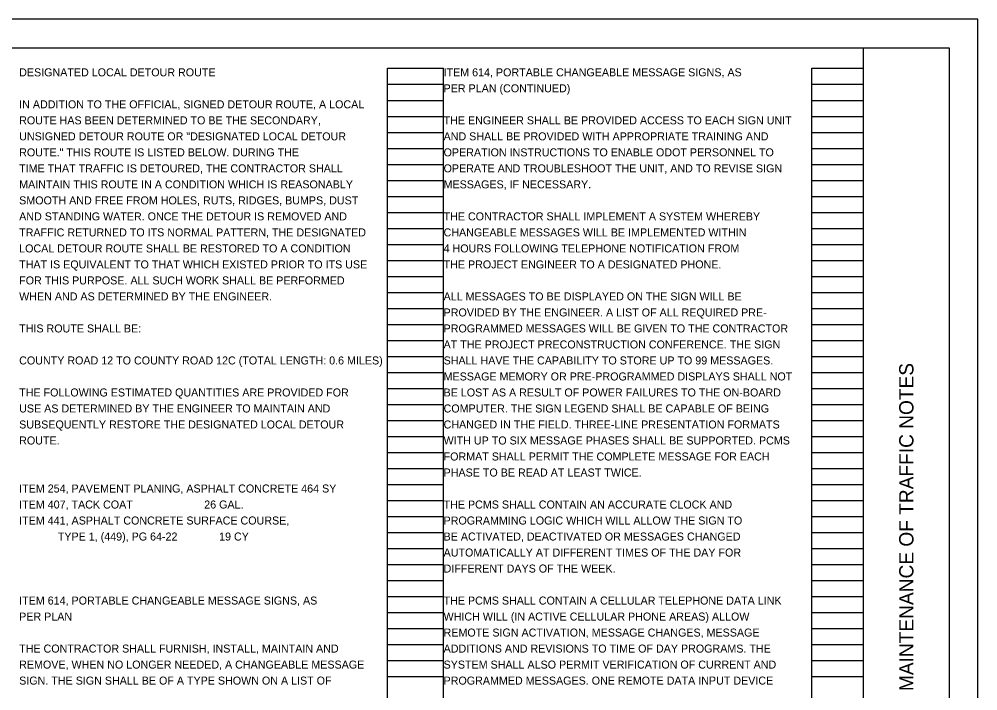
# Model space of a CAD drawing. Extents: x 0 to 34, y 0 to 22.
# Drawn here: x 17.24 to 34, y 10.25 to 22 of the extents above; entities that cross this region are included whole.
import ezdxf

# ---------------------------------------------------------------- set-up
doc = ezdxf.new("R2010")
doc.units = 0
for name, color, linetype in [('SH_Border', 7, 'Continuous'), ('SH_Cut_Line', 7, 'Continuous'), ('SH_Data', 7, 'Continuous'), ('SH_Text', 7, 'Continuous')]:
    doc.layers.add(name, color=color, linetype=linetype)

msp = doc.modelspace()

# ---------------------------------------------------------------- linework, layer by layer
at = {"layer": 'SH_Border'}
msp.add_line((32, 0.5), (32, 21.5), dxfattribs=at)
msp.add_lwpolyline([(1.5, 21.5), (33.5, 21.5), (33.5, 0.5), (1.5, 0.5)], close=True, dxfattribs=at)
at = {"layer": 'SH_Cut_Line'}
msp.add_lwpolyline([(0, 0), (34, 0), (34, 22), (0, 22)], close=True, dxfattribs=at)
at = {"layer": 'SH_Data'}
for p, q in [((23.68, 0.98), (23.68, 21.14)), ((23.68, 21.14), (24.66, 21.14)), ((24.66, 0.98), (24.66, 21.14)), ((31.1, 0.98), (31.1, 21.14)), ((31.1, 21.14), (32, 21.14)), ((32, 0.98), (32, 21.14)), ((23.68, 20.86), (24.66, 20.86)), ((31.1, 20.86), (32, 20.86)), ((23.68, 20.58), (24.66, 20.58)), ((31.1, 20.58), (32, 20.58)), ((23.68, 20.3), (24.66, 20.3)), ((31.1, 20.3), (32, 20.3)), ((23.68, 20.02), (24.66, 20.02)), ((31.1, 20.02), (32, 20.02)), ((23.68, 19.74), (24.66, 19.74)), ((31.1, 19.74), (32, 19.74)), ((23.68, 19.46), (24.66, 19.46)), ((31.1, 19.46), (32, 19.46)), ((23.68, 19.18), (24.66, 19.18)), ((31.1, 19.18), (32, 19.18)), ((23.68, 18.9), (24.66, 18.9)), ((31.1, 18.9), (32, 18.9)), ((23.68, 18.62), (24.66, 18.62)), ((31.1, 18.62), (32, 18.62)), ((23.68, 18.34), (24.66, 18.34)), ((31.1, 18.34), (32, 18.34)), ((23.68, 18.06), (24.66, 18.06)), ((31.1, 18.06), (32, 18.06)), ((23.68, 17.78), (24.66, 17.78)), ((31.1, 17.78), (32, 17.78)), ((23.68, 17.5), (24.66, 17.5)), ((31.1, 17.5), (32, 17.5)), ((23.68, 17.22), (24.66, 17.22)), ((31.1, 17.22), (32, 17.22)), ((23.68, 16.94), (24.66, 16.94)), ((31.1, 16.94), (32, 16.94)), ((23.68, 16.66), (24.66, 16.66)), ((31.1, 16.66), (32, 16.66)), ((23.68, 16.38), (24.66, 16.38)), ((31.1, 16.38), (32, 16.38)), ((23.68, 16.1), (24.66, 16.1)), ((31.1, 16.1), (32, 16.1)), ((23.68, 15.82), (24.66, 15.82)), ((31.1, 15.82), (32, 15.82)), ((23.68, 15.54), (24.66, 15.54)), ((31.1, 15.54), (32, 15.54)), ((23.68, 15.26), (24.66, 15.26)), ((31.1, 15.26), (32, 15.26)), ((23.68, 14.98), (24.66, 14.98)), ((31.1, 14.98), (32, 14.98)), ((23.68, 14.7), (24.66, 14.7)), ((31.1, 14.7), (32, 14.7)), ((23.68, 14.42), (24.66, 14.42)), ((31.1, 14.42), (32, 14.42)), ((23.68, 14.14), (24.66, 14.14)), ((31.1, 14.14), (32, 14.14)), ((23.68, 13.86), (24.66, 13.86)), ((31.1, 13.86), (32, 13.86)), ((23.68, 13.58), (24.66, 13.58)), ((31.1, 13.58), (32, 13.58)), ((23.68, 13.3), (24.66, 13.3)), ((31.1, 13.3), (32, 13.3)), ((23.68, 13.02), (24.66, 13.02)), ((31.1, 13.02), (32, 13.02)), ((23.68, 12.74), (24.66, 12.74)), ((31.1, 12.74), (32, 12.74)), ((23.68, 12.46), (24.66, 12.46)), ((31.1, 12.46), (32, 12.46)), ((23.68, 12.18), (24.66, 12.18)), ((31.1, 12.18), (32, 12.18)), ((23.68, 11.9), (24.66, 11.9)), ((31.1, 11.9), (32, 11.9)), ((23.68, 11.62), (24.66, 11.62)), ((31.1, 11.62), (32, 11.62)), ((23.68, 11.34), (24.66, 11.34)), ((31.1, 11.34), (32, 11.34)), ((23.68, 11.06), (24.66, 11.06)), ((31.1, 11.06), (32, 11.06)), ((23.68, 10.78), (24.66, 10.78)), ((31.1, 10.78), (32, 10.78)), ((23.68, 10.5), (24.66, 10.5)), ((31.1, 10.5), (32, 10.5))]:
    msp.add_line(p, q, dxfattribs=at)

# ---------------------------------------------------------------- texts
msp.add_text('MAINTENANCE OF TRAFFIC NOTES', height=0.25, rotation=90, dxfattribs=at).set_placement((32.875, 10.247))
at = {"layer": 'SH_Text'}
for s, p in [('DESIGNATED LOCAL DETOUR ROUTE', (17.24, 21)), ('ITEM 614, PORTABLE CHANGEABLE MESSAGE SIGNS, AS', (24.66, 21)), ('PER PLAN (CONTINUED)', (24.66, 20.72)), ('IN ADDITION TO THE OFFICIAL, SIGNED DETOUR ROUTE, A LOCAL', (17.24, 20.44)), ('ROUTE HAS BEEN DETERMINED TO BE THE SECONDARY,', (17.24, 20.16)), ('THE ENGINEER SHALL BE PROVIDED ACCESS TO EACH SIGN UNIT', (24.66, 20.16)), ('UNSIGNED DETOUR ROUTE OR "DESIGNATED LOCAL DETOUR', (17.24, 19.88)), ('AND SHALL BE PROVIDED WITH APPROPRIATE TRAINING AND', (24.66, 19.88)), ('ROUTE." THIS ROUTE IS LISTED BELOW. DURING THE', (17.24, 19.6)), ('OPERATION INSTRUCTIONS TO ENABLE ODOT PERSONNEL TO', (24.66, 19.6)), ('TIME THAT TRAFFIC IS DETOURED, THE CONTRACTOR SHALL', (17.24, 19.32)), ('OPERATE AND TROUBLESHOOT THE UNIT, AND TO REVISE SIGN', (24.66, 19.32)), ('MAINTAIN THIS ROUTE IN A CONDITION WHICH IS REASONABLY', (17.24, 19.04)), ('MESSAGES, IF NECESSARY.', (24.66, 19.04)), ('SMOOTH AND FREE FROM HOLES, RUTS, RIDGES, BUMPS, DUST', (17.24, 18.76)), ('AND STANDING WATER. ONCE THE DETOUR IS REMOVED AND', (17.24, 18.48)), ('THE CONTRACTOR SHALL IMPLEMENT A SYSTEM WHEREBY', (24.66, 18.48)), ('TRAFFIC RETURNED TO ITS NORMAL PATTERN, THE DESIGNATED', (17.24, 18.2)), ('CHANGEABLE MESSAGES WILL BE IMPLEMENTED WITHIN', (24.66, 18.2)), ('LOCAL DETOUR ROUTE SHALL BE RESTORED TO A CONDITION', (17.24, 17.92)), ('4 HOURS FOLLOWING TELEPHONE NOTIFICATION FROM', (24.66, 17.92)), ('THAT IS EQUIVALENT TO THAT WHICH EXISTED PRIOR TO ITS USE', (17.24, 17.64)), ('THE PROJECT ENGINEER TO A DESIGNATED PHONE.', (24.66, 17.64)), ('FOR THIS PURPOSE. ALL SUCH WORK SHALL BE PERFORMED', (17.24, 17.36)), ('WHEN AND AS DETERMINED BY THE ENGINEER.', (17.24, 17.08)), ('ALL MESSAGES TO BE DISPLAYED ON THE SIGN WILL BE', (24.66, 17.08)), ('PROVIDED BY THE ENGINEER. A LIST OF ALL REQUIRED PRE-', (24.66, 16.8)), ('THIS ROUTE SHALL BE:', (17.24, 16.52)), ('PROGRAMMED MESSAGES WILL BE GIVEN TO THE CONTRACTOR', (24.66, 16.52)), ('AT THE PROJECT PRECONSTRUCTION CONFERENCE. THE SIGN', (24.66, 16.24)), ('COUNTY ROAD 12 TO COUNTY ROAD 12C (TOTAL LENGTH: 0.6 MILES)', (17.24, 15.96)), ('SHALL HAVE THE CAPABILITY TO STORE UP TO 99 MESSAGES.', (24.66, 15.96)), ('MESSAGE MEMORY OR PRE-PROGRAMMED DISPLAYS SHALL NOT', (24.66, 15.68)), ('THE FOLLOWING ESTIMATED QUANTITIES ARE PROVIDED FOR', (17.24, 15.4)), ('BE LOST AS A RESULT OF POWER FAILURES TO THE ON-BOARD', (24.66, 15.4)), ('USE AS DETERMINED BY THE ENGINEER TO MAINTAIN AND', (17.24, 15.12)), ('COMPUTER. THE SIGN LEGEND SHALL BE CAPABLE OF BEING', (24.66, 15.12)), ('SUBSEQUENTLY RESTORE THE DESIGNATED LOCAL DETOUR', (17.24, 14.84)), ('CHANGED IN THE FIELD. THREE-LINE PRESENTATION FORMATS', (24.66, 14.84)), ('ROUTE.', (17.24, 14.56)), ('WITH UP TO SIX MESSAGE PHASES SHALL BE SUPPORTED. PCMS', (24.66, 14.56)), ('FORMAT SHALL PERMIT THE COMPLETE MESSAGE FOR EACH', (24.66, 14.28)), ('PHASE TO BE READ AT LEAST TWICE.', (24.66, 14)), ('ITEM 254, PAVEMENT PLANING, ASPHALT CONCRETE 464 SY', (17.24, 13.72)), ('ITEM 407, TACK COAT                        26 GAL.', (17.24, 13.44)), ('THE PCMS SHALL CONTAIN AN ACCURATE CLOCK AND', (24.66, 13.44)), ('ITEM 441, ASPHALT CONCRETE SURFACE COURSE,', (17.24, 13.16)), ('PROGRAMMING LOGIC WHICH WILL ALLOW THE SIGN TO', (24.66, 13.16)), ('             TYPE 1, (449), PG 64-22              19 CY', (17.24, 12.88)), ('BE ACTIVATED, DEACTIVATED OR MESSAGES CHANGED', (24.66, 12.88)), ('AUTOMATICALLY AT DIFFERENT TIMES OF THE DAY FOR', (24.66, 12.6)), ('DIFFERENT DAYS OF THE WEEK.', (24.66, 12.32)), ('ITEM 614, PORTABLE CHANGEABLE MESSAGE SIGNS, AS', (17.24, 11.76)), ('THE PCMS SHALL CONTAIN A CELLULAR TELEPHONE DATA LINK', (24.66, 11.76)), ('PER PLAN', (17.24, 11.48)), ('WHICH WILL (IN ACTIVE CELLULAR PHONE AREAS) ALLOW', (24.66, 11.48)), ('REMOTE SIGN ACTIVATION, MESSAGE CHANGES, MESSAGE', (24.66, 11.2)), ('THE CONTRACTOR SHALL FURNISH, INSTALL, MAINTAIN AND', (17.24, 10.92)), ('ADDITIONS AND REVISIONS TO TIME OF DAY PROGRAMS. THE', (24.66, 10.92)), ('REMOVE, WHEN NO LONGER NEEDED, A CHANGEABLE MESSAGE', (17.24, 10.64)), ('SYSTEM SHALL ALSO PERMIT VERIFICATION OF CURRENT AND', (24.66, 10.64)), ('SIGN. THE SIGN SHALL BE OF A TYPE SHOWN ON A LIST OF', (17.24, 10.36)), ('PROGRAMMED MESSAGES. ONE REMOTE DATA INPUT DEVICE', (24.66, 10.36))]:
    msp.add_text(s, height=0.14, dxfattribs=at).set_placement(p)

doc.saveas('drawing.dxf')
